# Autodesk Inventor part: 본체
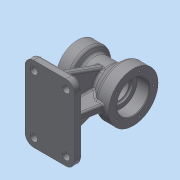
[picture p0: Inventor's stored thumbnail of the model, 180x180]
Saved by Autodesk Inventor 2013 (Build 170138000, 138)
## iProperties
Created: 2015-08
Part Number: 본체
Material: 일반
Document SubType Name: Modeling
Designer: WINDOWS7
Density: 1 g/cm^3
Author: WINDOWS7
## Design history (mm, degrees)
sketch "스케치1"
  geometry: L1 (-45, 0)-(45, 0); L2 (-45, 0)-(-45, 35); L3 (-45, 35)-(-25, 35); L4 (-25, 35)-(-19.804, 26); L5 (-19.804, 26)-(8.315, 26); L6 (8.315, 26)-(25, 40); L7 (25, 40)-(45, 40); L8 (45, 40)-(45, 0); 2 further points
  constraints: 16 end point, 3 parallel, 2 perpendicular, 1 coincident, 1 horizontal, 1 midpoint
  dimensions: "d0" = 90 distance of L1.start L1.end; "d2" = 80 diameter of L7 L1; "d3" = 70 diameter of L3 L1; "d4" = 20 distance of L2.end L3.end; "d5" = 20 distance of L6.end L7.end; "d6" = 60 deg angle of L5 L4; "d7" = 40 deg angle of L5 L6; "d8" = 52 diameter of L5 L1
revolve "회전1" sketch "스케치1" stored, may be unused: angle "d9" = 90 deg
node "작업 평면1"
sketch "스케치2"
  geometry: L1 (-40, 61)-(40, 61); L2 (40, 61)-(40, -61); L3 (40, -61)-(-40, -61); L4 (-40, -61)-(-40, 61); 3 further points
  constraints: 8 end point, 2 midpoint, 2 parallel, 1 horizontal, 1 horizontal alignment, 1 perpendicular, 1 vertical alignment
  dimensions: "d11" = 80 distance of L1.start L1.end; "d13" = 122 distance of L1.end L2.end
extrude "돌출1" join sketch "스케치2" distance "d14" = 12; taper "d15" = 0 deg
node "작업 평면2"
sketch "스케치3"
  geometry: L1 (-40, -90)-(40, -90) reference; L2 (-40, -90)-(-40, -78) reference; L3 (40, -78)-(-40, -78) reference; L4 (40, -90)-(40, -78) reference; L5 (30, -78)-(41.917, -10.416); L6 (41.917, -10.416)-(-30, -10.416); L7 (-30, -10.416)-(-30, -78); 1 further point
  constraints: 6 end point, 2 perpendicular, 2 point on line
  dimensions: "d17" = 10 distance of L3.start L5.start; "d18" = 80 deg angle of L3 L5; "d19" = 10 distance from line of L7 L2.end; "d20" = 71.91687 distance of L5.end L6.end
extrude "돌출2" join sketch "스케치3" stored distance "d21" = 12; taper "d22" = 0 deg
sketch "스케치4"
  geometry: L1 (-90, 61)-(-90, -61) reference; L2 (-90, 61)-(-78, 61) reference; L3 (-78, -61)-(-78, 61) reference; L4 (-90, -61)-(-78, -61) reference; L5 (-78, -51)-(7.172, -20); L6 (7.172, -20)-(7.172, 20); L7 (7.172, 20)-(-78, 51); 1 further point
  constraints: 6 end point, 2 point on line, 1 equal length, 1 perpendicular
  dimensions: "d23" = 10 distance of L3.start L5.start; "d24" = 70 deg angle of L3 L5; "d25" = 10 distance of L2.end L7.end; "d26" = 40 distance of L5.end L6.end
extrude "돌출3" join sketch "스케치4" stored distance "d27" = 12; taper "d28" = 0 deg
sketch "스케치5"
  geometry: L1 (40, 61)-(-40, 61) reference; L2 (40, -61)-(40, 61) reference; C1 r 6 at (26, 47); C2 r 6 at (26, -47); C3 r 6 at (-26, -47); C4 r 6 at (-26, 47); 1 further point
  constraints: 4 centre point, 3 equal radius, 2 horizontal alignment, 2 vertical alignment
  dimensions: "d29" = 12 diameter of C1; "d31" = 14 distance from line of L1 C1.centre; "d32" = 94 distance of C2.centre C1.centre; "d33" = 14 distance from line of L2 C2.centre; "d34" = 52 distance of C3.centre C2.centre
extrude "돌출4" cut sketch "스케치5" stored distance "d35" = 12; taper "d36" = 0 deg
sketch "스케치6"
  geometry: L1 (-90, 61)-(-90, -61) reference; L2 (-78, -61)-(-78, 61) reference; L3 (-54, 30)-(-60, 30); L4 (-54, 18)-(-60, 18); L5 (-54, -18)-(-60, -18); L6 (-54, -30)-(-60, -30); A1 r 6 centre (-60, 24) between (-60, 30) and (-60, 18); A2 r 6 centre (-54, 24) between (-54, 18) and (-54, 30); A3 r 6 centre (-60, -24) between (-60, -18) and (-60, -30); A4 r 6 centre (-54, -24) between (-54, -30) and (-54, -18); 3 further points
  constraints: 8 end point, 8 point on circle, 4 centre point, 4 tangent, 3 equal radius, 3 parallel, 2 horizontal alignment, 1 coincident, 1 midpoint, 1 perpendicular
  dimensions: "d41" = 24 vertical distance of point (-90, 0) point (-60, 24); "d42" = 12 diameter of A1; "d43" = 18 distance from line of A1.centre L2; "d44" = 18 dimension on A1 A2; "d45" = 18 dimension on A3 A4; "d46" = 18 distance from line of L2 A3.centre; "d47" = 48 distance of A3.centre point (-60, 24)
extrude "돌출5" cut sketch "스케치6" stored distance "d48" = 12; taper "d49" = 0 deg
fillet "모깎기1" dims "d50" = 14
sketch "스케치7"
  geometry: C1 r 40 at (0, 0) reference; C2 r 26 at (0, 0)
  constraints: 1 centre point, 1 coincident
  dimensions: "d51" = 52 diameter of C2
extrude "돌출6" cut sketch "스케치7" distance "d53" = 20; taper "d54" = 0 deg
sketch "스케치8"
  geometry: C1 r 26 at (0, 0) reference; C2 r 19 at (0, 0)
  constraints: 1 centre point, 1 coincident
  dimensions: "d55" = 38 diameter of C2
extrude "돌출7" cut sketch "스케치8" distance "d57" = 3; taper "d58" = 0 deg
sketch "스케치9"
  geometry: C1 r 35 at (0, 0) reference; C2 r 20 at (0, 0)
  constraints: 1 centre point, 1 coincident
  dimensions: "d59" = 40 diameter of C2
extrude "돌출8" cut sketch "스케치9" distance "d61" = 17; taper "d62" = 0 deg
sketch "스케치10"
  geometry: C1 r 20 at (0, 0) reference; C2 r 16 at (0, 0)
  constraints: 1 centre point, 1 coincident
  dimensions: "d63" = 32 diameter of C2
extrude "돌출9" cut sketch "스케치10" stored distance "d65" = 17; taper "d66" = 0 deg
chamfer "모따기1" distance "d67" = 1; stored, may be unused: second distance "d68" = 2, angle "d69" = 45 deg
fillet "모깎기2" dims "d70" = 3
fillet "모깎기3" dims "d71" = 3
fillet "모깎기4" dims "d72" = 0.3
fillet "모깎기5" dims "d73" = 5
sketch "스케치11" dims "d74" = 54
  geometry: C1 r 35 at (0, 0) reference; C2 r 21 at (0, 0) reference; 6 further points
  constraints: 2 vertical alignment, 1 coincident, 8 other
  dimensions: "d78" = 360 deg dimension on C1.centre point (0, 27) (derived)
hole "구멍1" sketch "스케치11" at (0, 27), (-25.679, 8.343), (-15.87, -21.843), (15.87, -21.843), (25.679, 8.343) diameter "d80" = 3.242; stored, may be unused: countersink angle "d84" = 90 deg, drill point angle "d86" = 118 deg; dims "d81" = 10, "d82" = 4, "d83" = 2, "d85" = 13
sketch "스케치12" dims "d87" = 66
  geometry: C1 r 40 at (0, 0) reference; C2 r 27 at (0, 0) reference; 6 further points
  constraints: 2 vertical alignment, 1 coincident, 8 other
  dimensions: "d91" = 360 deg dimension on C1.centre point (0, 33) (derived)
hole "구멍2" sketch "스케치12" at (0, 33), (-31.385, 10.198), (-19.397, -26.698), (19.397, -26.698), (31.385, 10.198) diameter "d93" = 3.242; stored, may be unused: countersink angle "d97" = 90 deg, drill point angle "d99" = 118 deg; dims "d94" = 10, "d95" = 4, "d96" = 2, "d98" = 13
fillet "모깎기6" dims "d100" = 3
fillet "모깎기7" dims "d101" = 3
sketch "스케치13"
  geometry: L1 (-30, -37.881)-(-30, -75) reference; L2 (26, -78)-(-26, -78) reference; 2 further points
  constraints: 1 other
  dimensions: "d102" = 24 distance from line of point (-14, -54) L2; "d103" = 16 distance from line of point (-14, -54) L1
feature "엠보싱1" sketch "스케치13" dims "d0" = 90, "d2" = 80, "d3" = 70, "d4" = 20, "d5" = 20, "d6" = 60 deg, "d7" = 40 deg, "d8" = 52, "d104" = 0.5, "d105" = 0
node "솔리드1"
node "투영된 루프1"
node "투영된 루프2"
other parameters: "d16" = 0
